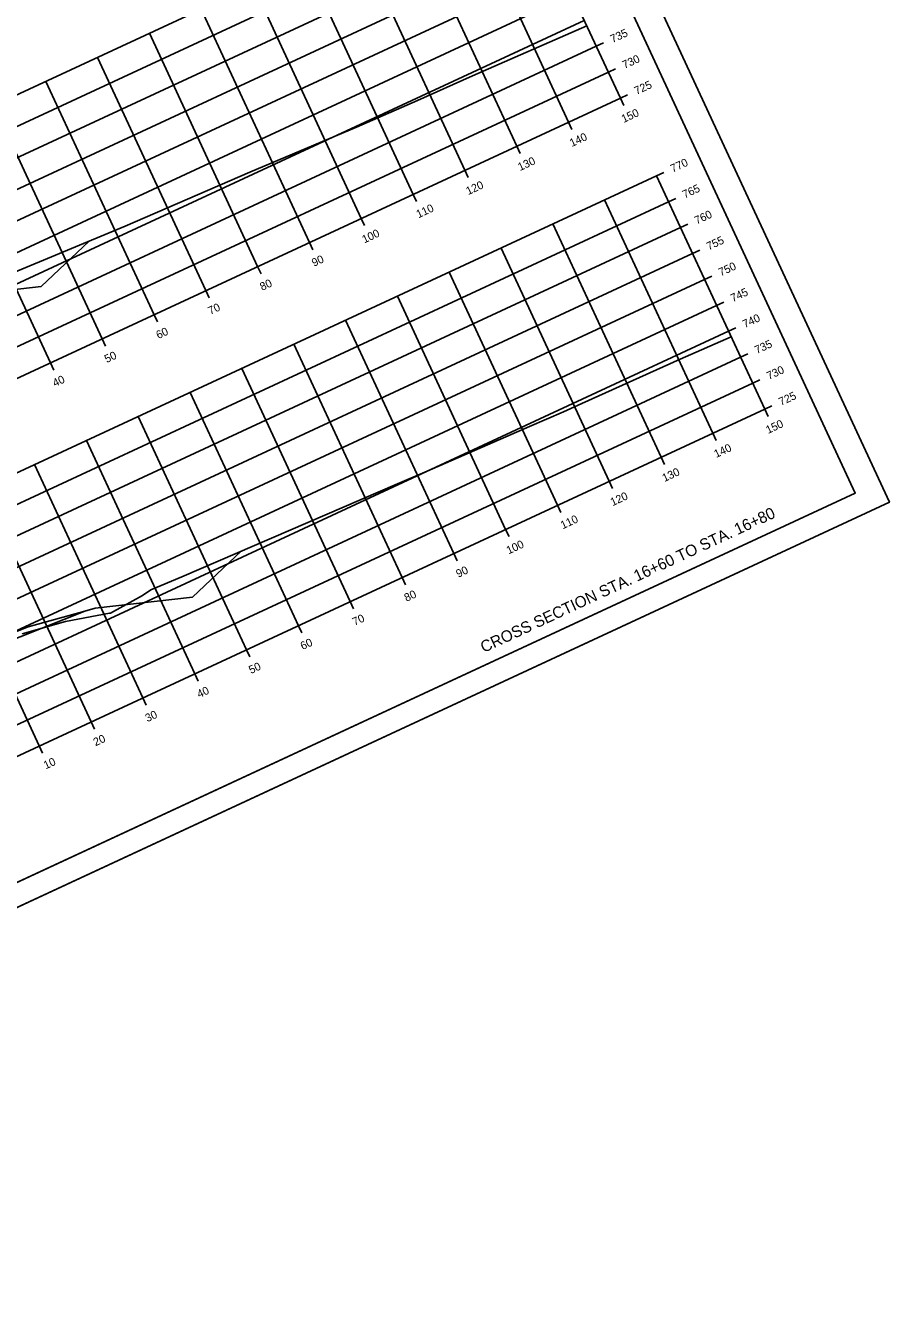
# Model space of a CAD drawing. Extents: x 1354696 to 1366163, y 660729 to 670380.
# Drawn here: x 1358423.4 to 1358574.6, y 665349.1 to 665572.9 of the extents above; entities that cross this region are included whole.
import ezdxf

# ---------------------------------------------------------------- set-up
doc = ezdxf.new("R2010")
doc.units = 0
for name, color, linetype in [('Default', 7, 'Continuous'), ('R_Alt Surface', 7, 'Continuous'), ('R_Axis', 7, 'Continuous'), ('R_Axis Annot', 7, 'Continuous'), ('R_Border', 7, 'Continuous'), ('R_Draft', 7, 'Continuous'), ('R_Exist Surface', 7, 'Continuous'), ('R_Fin Surface', 7, 'Continuous'), ('R_Grid', 7, 'Continuous'), ('R_No Plot', 7, 'Continuous')]:
    doc.layers.add(name, color=color, linetype=linetype)

msp = doc.modelspace()

# ---------------------------------------------------------------- linework, layer by layer
at = {"layer": 'Default'}
msp.add_lwpolyline([(1358418.73, 665464.43), (1358418.32, 665465.29), (1358418.25, 665465.44), (1358423.83, 665467.67), (1358433.77, 665470.41)], close=True, dxfattribs=at)
at = {"layer": 'R_Alt Surface'}
msp.add_lwpolyline([(1358383.18, 665448.92), (1358398.23, 665456.28), (1358397.84, 665457.15), (1358408.08, 665461.22), (1358418.32, 665465.29), (1358418.73, 665464.43), (1358433.77, 665470.41)], dxfattribs=at)
at = {"layer": 'R_Axis'}
for p, q in [((1358527.52, 665560.17), (1358508.57, 665600.99)), ((1358524.57, 665569.83), (1358523.3, 665569.24)), ((1358526.68, 665565.3), (1358525.41, 665564.71)), ((1358255.41, 665433.84), (1358527.52, 665560.17)), ((1358528.79, 665560.76), (1358527.52, 665560.17)), ((1358528.11, 665558.9), (1358527.52, 665560.17)), ((1358519.04, 665554.69), (1358518.45, 665555.96)), ((1358509.96, 665550.48), (1358509.38, 665551.75)), ((1358500.89, 665546.27), (1358500.31, 665547.54)), ((1358535.1, 665547.16), (1358533.83, 665546.57)), ((1358552.78, 665505.75), (1358533.83, 665546.57)), ((1358491.82, 665542.06), (1358491.24, 665543.33)), ((1358537.21, 665542.62), (1358535.94, 665542.03)), ((1358482.75, 665537.85), (1358482.16, 665539.12)), ((1358539.31, 665538.09), (1358538.04, 665537.5)), ((1358473.68, 665533.64), (1358473.09, 665534.91)), ((1358541.42, 665533.55), (1358540.15, 665532.96)), ((1358464.61, 665529.43), (1358464.02, 665530.7)), ((1358543.52, 665529.02), (1358542.25, 665528.43)), ((1358455.54, 665525.21), (1358454.95, 665526.48)), ((1358545.63, 665524.48), (1358544.36, 665523.89)), ((1358446.47, 665521), (1358445.88, 665522.27)), ((1358547.74, 665519.95), (1358546.47, 665519.36)), ((1358437.4, 665516.79), (1358436.81, 665518.06)), ((1358549.84, 665515.41), (1358548.57, 665514.82)), ((1358428.33, 665512.58), (1358427.74, 665513.85)), ((1358551.95, 665510.88), (1358550.68, 665510.29)), ((1358280.68, 665379.42), (1358552.78, 665505.75)), ((1358554.05, 665506.34), (1358552.78, 665505.75)), ((1358553.37, 665504.48), (1358552.78, 665505.75)), ((1358544.3, 665500.27), (1358543.71, 665501.54)), ((1358535.23, 665496.06), (1358534.64, 665497.33)), ((1358526.16, 665491.85), (1358525.57, 665493.12)), ((1358517.09, 665487.64), (1358516.5, 665488.91)), ((1358508.02, 665483.43), (1358507.43, 665484.7)), ((1358498.95, 665479.22), (1358498.36, 665480.49)), ((1358489.88, 665475.01), (1358489.29, 665476.27)), ((1358480.81, 665470.79), (1358480.22, 665472.06)), ((1358471.74, 665466.58), (1358471.15, 665467.85)), ((1358462.67, 665462.37), (1358462.08, 665463.64)), ((1358453.6, 665458.16), (1358453.01, 665459.43)), ((1358444.53, 665453.95), (1358443.94, 665455.22)), ((1358435.46, 665449.74), (1358434.87, 665451.01)), ((1358426.39, 665445.53), (1358425.8, 665446.8))]:
    msp.add_line(p, q, dxfattribs=at)
at = {"layer": 'R_Border'}
for q in [(1358482.1, 665677.41), (1358281.84, 665357.91)]:
    msp.add_line((1358568.62, 665491.06), q, dxfattribs=at)
at = {"layer": 'R_Exist Surface'}
for points in [[(1358419.96, 665529.06), (1358440.81, 665537.78), (1358462.65, 665547.21), (1358481.31, 665555.09), (1358492, 665559.74), (1358501.63, 665564.06), (1358521.65, 665572.81)], [(1358422.83, 665466.45), (1358430.36, 665468.61), (1358438.09, 665470.02), (1358438.24, 665470.04), (1358443.84, 665473.12), (1358445.35, 665474.13), (1358450.78, 665476.41), (1358488.48, 665492.7), (1358493.7, 665494.91), (1358511.63, 665502.71), (1358517.53, 665505.28), (1358520.78, 665506.74), (1358537.99, 665514.46), (1358546.93, 665518.37)]]:
    msp.add_lwpolyline(points, dxfattribs=at)
at = {"layer": 'R_Fin Surface'}
for points in [[(1358309.93, 665488.13), (1358310.38, 665488.18), (1358318.89, 665489.14), (1358320.62, 665489.34), (1358345.54, 665492.17), (1358356.8, 665502.8), (1358357.75, 665503.44), (1358366.85, 665509.66), (1358372.44, 665511.87), (1358382.69, 665515.91), (1358392.94, 665519.96), (1358398.53, 665522.17), (1358408.71, 665524.98), (1358410.25, 665525.4), (1358426.1, 665527.2), (1358434.53, 665535.15)], [(1358335.69, 665433.1), (1358336.72, 665433.22), (1358365.98, 665436.53), (1358370.28, 665437.02), (1358382.14, 665448.21), (1358382.14, 665448.21), (1358383.18, 665448.92), (1358392.19, 665455.08), (1358397.77, 665457.3), (1358408.01, 665461.37), (1358418.25, 665465.44), (1358423.83, 665467.67), (1358433.77, 665470.41), (1358435.56, 665470.9), (1358435.56, 665470.9), (1358452.6, 665472.84), (1358461.11, 665480.87)]]:
    msp.add_lwpolyline(points, dxfattribs=at)
at = {"layer": 'R_Grid'}
for p, q in [((1358236.46, 665474.66), (1358508.57, 665600.99)), ((1358527.52, 665560.17), (1358508.57, 665600.99)), ((1358238.57, 665470.12), (1358510.67, 665596.45)), ((1358518.45, 665555.96), (1358499.5, 665596.78)), ((1358509.38, 665551.75), (1358490.43, 665592.57)), ((1358240.67, 665465.59), (1358512.78, 665591.92)), ((1358500.31, 665547.54), (1358481.36, 665588.36)), ((1358242.78, 665461.05), (1358514.88, 665587.38)), ((1358491.24, 665543.33), (1358472.29, 665584.14)), ((1358244.88, 665456.52), (1358516.99, 665582.85)), ((1358482.16, 665539.12), (1358463.22, 665579.93)), ((1358246.99, 665451.98), (1358519.09, 665578.31)), ((1358473.09, 665534.91), (1358454.15, 665575.72)), ((1358249.1, 665447.45), (1358521.2, 665573.78)), ((1358464.02, 665530.7), (1358445.08, 665571.51)), ((1358251.2, 665442.91), (1358523.3, 665569.24)), ((1358454.95, 665526.48), (1358436, 665567.3)), ((1358253.31, 665438.38), (1358525.41, 665564.71)), ((1358445.88, 665522.27), (1358426.93, 665563.09)), ((1358255.41, 665433.84), (1358527.52, 665560.17)), ((1358436.81, 665518.06), (1358417.86, 665558.88)), ((1358427.74, 665513.85), (1358408.79, 665554.67)), ((1358261.73, 665420.24), (1358533.83, 665546.57)), ((1358552.78, 665505.75), (1358533.83, 665546.57)), ((1358263.83, 665415.7), (1358535.94, 665542.03)), ((1358543.71, 665501.54), (1358524.76, 665542.36)), ((1358265.94, 665411.17), (1358538.04, 665537.5)), ((1358534.64, 665497.33), (1358515.69, 665538.15)), ((1358268.04, 665406.63), (1358540.15, 665532.96)), ((1358525.57, 665493.12), (1358506.62, 665533.93)), ((1358516.5, 665488.91), (1358497.55, 665529.72)), ((1358270.15, 665402.1), (1358542.25, 665528.43)), ((1358507.43, 665484.7), (1358488.48, 665525.51)), ((1358272.26, 665397.56), (1358544.36, 665523.89)), ((1358498.36, 665480.49), (1358479.41, 665521.3)), ((1358274.36, 665393.03), (1358546.47, 665519.36)), ((1358489.29, 665476.27), (1358470.34, 665517.09)), ((1358276.47, 665388.49), (1358548.57, 665514.82)), ((1358480.22, 665472.06), (1358461.27, 665512.88)), ((1358278.57, 665383.96), (1358550.68, 665510.29)), ((1358471.15, 665467.85), (1358452.2, 665508.67)), ((1358280.68, 665379.42), (1358552.78, 665505.75)), ((1358462.08, 665463.64), (1358443.13, 665504.46)), ((1358453.01, 665459.43), (1358434.06, 665500.25)), ((1358443.94, 665455.22), (1358424.99, 665496.04)), ((1358434.87, 665451.01), (1358415.92, 665491.82)), ((1358425.8, 665446.8), (1358406.85, 665487.61))]:
    msp.add_line(p, q, dxfattribs=at)
at = {"layer": 'R_No Plot'}
msp.add_line((1358272.27, 665349.08), (1358574.61, 665489.45), dxfattribs=at)
for points in [[(1358182.43, 665542.58), (1358484.77, 665682.95), (1358574.61, 665489.45), (1358272.27, 665349.08)], [(1358407.49, 665642.77), (1358425.29, 665651.03), (1358429.45, 665642.07), (1358444.06, 665648.86), (1358465.1, 665658.63), (1358477.07, 665633.14), (1358498.12, 665642.91), (1358568.62, 665491.06), (1358281.84, 665357.91), (1358195.32, 665544.27)]]:
    msp.add_lwpolyline(points, close=True, dxfattribs=at)

# ---------------------------------------------------------------- texts
at = {"layer": 'R_Axis Annot'}
for s, p in [('735', (1358526.14, 665569.79)), ('730', (1358528.24, 665565.25)), ('725', (1358530.35, 665560.72)), ('150', (1358528.09, 665555.81)), ('140', (1358519.02, 665551.6)), ('130', (1358509.95, 665547.39)), ('770', (1358536.67, 665547.11)), ('120', (1358500.88, 665543.18)), ('765', (1358538.77, 665542.58)), ('110', (1358492.17, 665539.13)), ('760', (1358540.88, 665538.04)), ('100', (1358482.69, 665534.73)), ('755', (1358542.98, 665533.51)), ('90', (1358473.88, 665530.64)), ('750', (1358545.09, 665528.97)), ('80', (1358464.81, 665526.43)), ('745', (1358547.19, 665524.44)), ('70', (1358455.74, 665522.22)), ('740', (1358549.3, 665519.9)), ('60', (1358446.64, 665517.99)), ('735', (1358551.41, 665515.37)), ('50', (1358437.6, 665513.8)), ('730', (1358553.51, 665510.83)), ('40', (1358428.53, 665509.59)), ('725', (1358555.62, 665506.3)), ('150', (1358553.36, 665501.39)), ('140', (1358544.29, 665497.18)), ('130', (1358535.22, 665492.97)), ('120', (1358526.15, 665488.75)), ('110', (1358517.43, 665484.71)), ('100', (1358507.95, 665480.31)), ('90', (1358499.14, 665476.22)), ('80', (1358490.07, 665472.01)), ('70', (1358481, 665467.8)), ('60', (1358471.9, 665463.57)), ('50', (1358462.86, 665459.38)), ('40', (1358453.79, 665455.16)), ('30', (1358444.72, 665450.95)), ('20', (1358435.65, 665446.74)), ('10', (1358426.94, 665442.7))]:
    msp.add_text(s, height=1.4, rotation=24.9042, dxfattribs=at).set_placement(p)
at = {"layer": 'R_Draft'}
msp.add_text('CROSS SECTION STA. 16+60 TO STA. 16+80', height=2, rotation=24.9042, dxfattribs=at).set_placement((1358503.6, 665463.07))

doc.saveas('drawing.dxf')
